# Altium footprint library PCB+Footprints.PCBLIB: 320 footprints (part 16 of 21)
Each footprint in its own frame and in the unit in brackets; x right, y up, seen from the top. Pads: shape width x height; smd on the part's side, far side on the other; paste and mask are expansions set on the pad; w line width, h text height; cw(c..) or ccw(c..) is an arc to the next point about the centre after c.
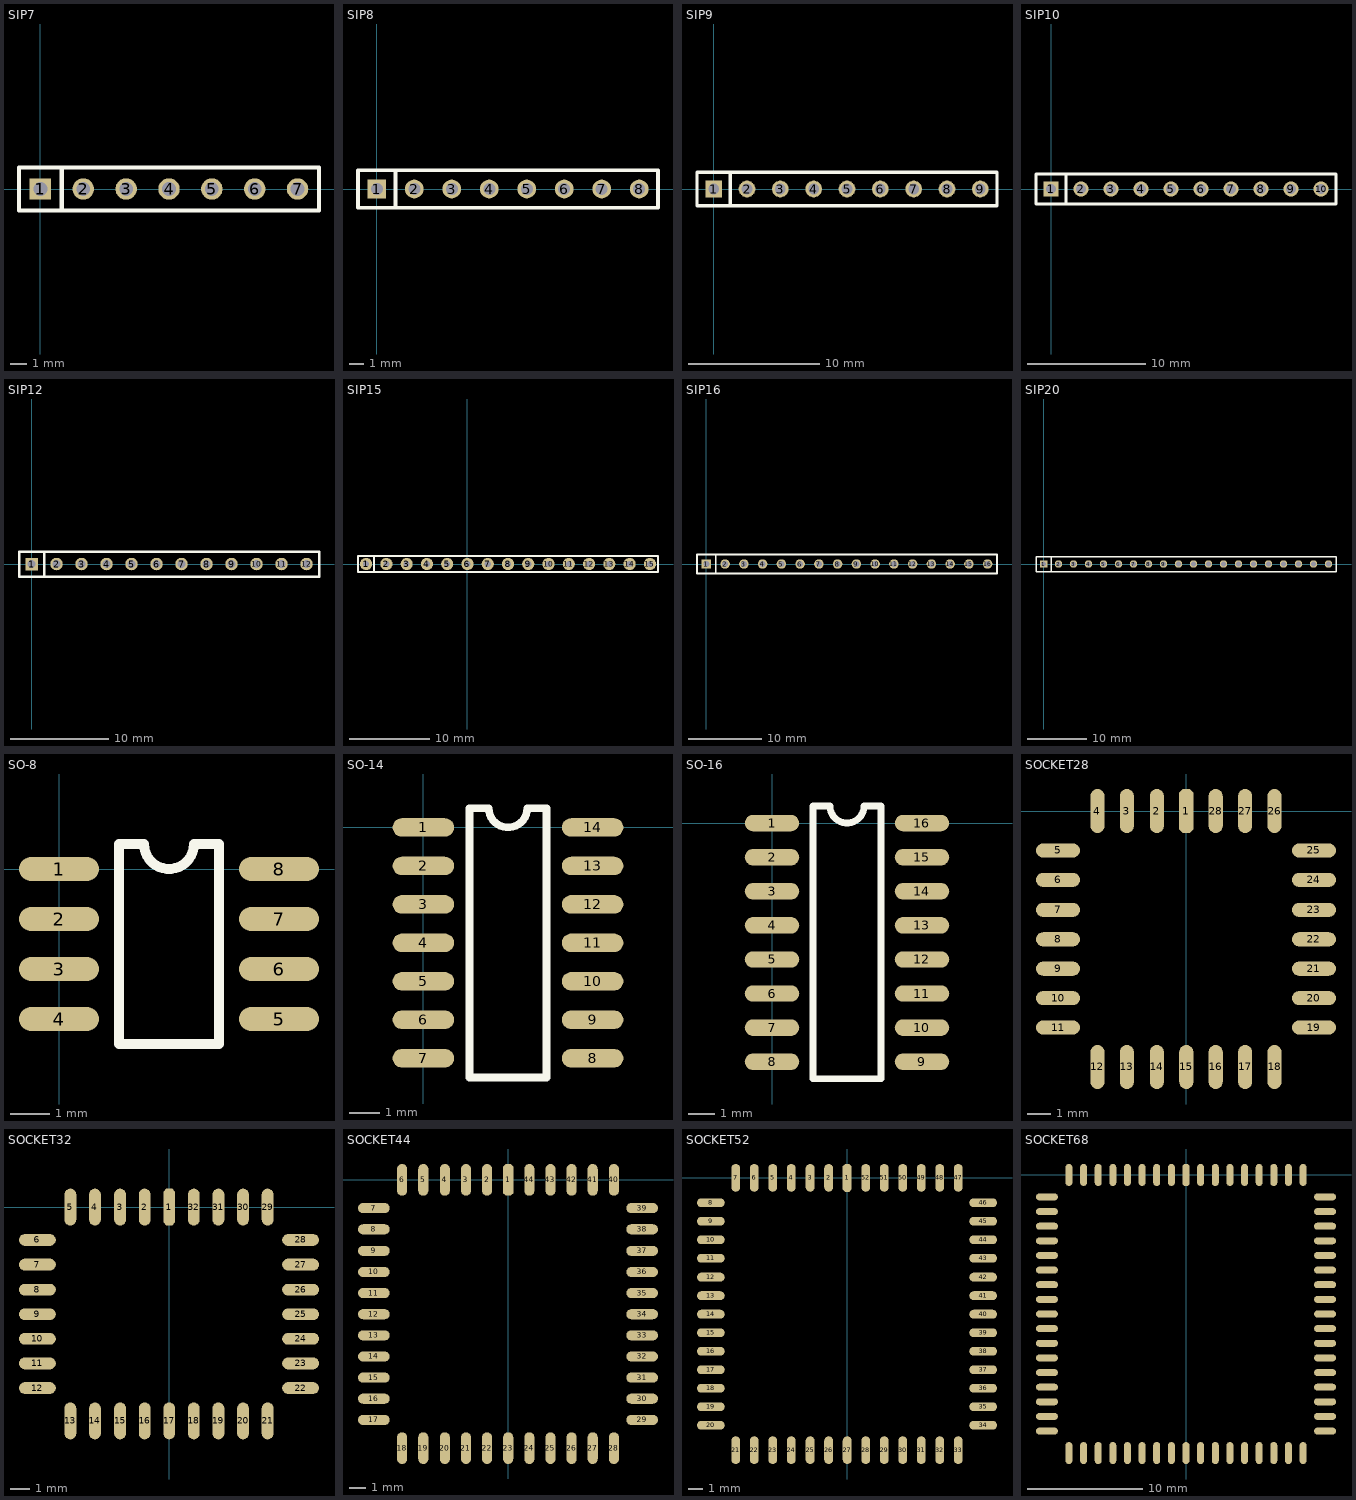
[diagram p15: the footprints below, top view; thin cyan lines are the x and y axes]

## SIP7 [mil]
pads (7):
  rect 50x50 hole 32: 1(0,0)
  round 50 hole 32: 2(100,0) 3(200,0) 4(300,0) 5(400,0) 6(500,0) 7(600,0)
TopOverlay:
  lines w10: 50,-50 50,50 ; -50,-50 650,-50 650,50 -50,50 -50,-50

## SIP8 [mil]
pads (8):
  rect 50x50 hole 32: 1(0,0)
  round 50 hole 32: 2(100,0) 3(200,0) 4(300,0) 5(400,0) 6(500,0) 7(600,0) 8(700,0)
TopOverlay:
  lines w10: 50,-50 50,50 ; -50,-50 -50,50 750,50 750,-50 -50,-50

## SIP9 [mil]
pads (9):
  rect 50x50 hole 32: 1(0,0)
  round 50 hole 32: 2(100,0) 3(200,0) 4(300,0) 5(400,0) 6(500,0) 7(600,0) 8(700,0) 9(800,0)
TopOverlay:
  lines w10: 50,-50 50,50 ; -50,-50 -50,50 850,50 850,-50 -50,-50

## SIP10 [mil]
pads (10):
  rect 50x50 hole 32: 1(0,0)
  round 50 hole 32: 2(100,0) 3(200,0) 4(300,0) 5(400,0) 6(500,0) 7(600,0) 8(700,0) 9(800,0) 10(900,0)
TopOverlay:
  lines w10: 50,-50 50,50 ; -50,-50 -50,50 950,50 950,-50 -50,-50

## SIP12 [mil]
pads (12):
  rect 50x50 hole 32: 1(0,0)
  round 50 hole 32: 2(100,0) 3(200,0) 4(300,0) 5(400,0) 6(500,0) 7(600,0) 8(700,0) 9(800,0) 10(900,0) 11(1000,0) 12(1100,0)
TopOverlay:
  lines w10: 50,-50 50,50 ; -50,-50 -50,50 1150,50 1150,-50 -50,-50

## SIP15 [mil]
pads (15):
  round 60 hole 30: 1(-500,0) 2(-400,0) 3(-300,0) 4(-200,0) 5(-100,0) 6(0,0) 7(100,0) 8(200,0) 9(300,0) 10(400,0) 11(500,0) 12(600,0) 13(700,0) 14(800,0) 15(900,0)
TopOverlay:
  lines w10: -460,-40 940,-40 940,40 -460,40 ; -460,-40 -460,40 ; -460,-40 -540,-40 -540,40 -460,40

## SIP16 [mil]
pads (16):
  rect 50x50 hole 32: 1(0,0)
  round 50 hole 32: 2(100,0) 3(200,0) 4(300,0) 5(400,0) 6(500,0) 7(600,0) 8(700,0) 9(800,0) 10(900,0) 11(1000,0) 12(1100,0) 13(1200,0) 14(1300,0) 15(1400,0) 16(1500,0)
TopOverlay:
  lines w10: 50,-50 50,50 ; -50,-50 1550,-50 1550,50 -50,50 -50,-50

## SIP20 [mil]
pads (20):
  rect 50x50 hole 32: 1(0,0)
  round 50 hole 32: 2(100,0) 3(200,0) 4(300,0) 5(400,0) 6(500,0) 7(600,0) 8(700,0) 9(800,0) 10(900,0) 11(1000,0) 12(1100,0) 13(1200,0) 14(1300,0) 15(1400,0) 16(1500,0) 17(1600,0) 18(1700,0) 19(1800,0) 20(1900,0)
TopOverlay:
  lines w10: 50,-50 50,50 ; -50,-50 -50,50 1950,50 1950,-50 -50,-50

## SO-8 [mil]
pads (8):
  oval 80x24 smd: 1(0,0) 2(0,-50) 3(0,-100) 4(0,-150) 5(220,-150) 6(220,-100) 7(220,-50) 8(220,0)
TopOverlay:
  lines w10: 60,-175 160,-175 160,25 135,25 cw(c110,25) 85,25 60,25 60,-175

## SO-14 [mil]
pads (14):
  oval 80x24 smd: 1(0,0) 2(0,-50) 3(0,-100) 4(0,-150) 5(0,-200) 6(0,-250) 7(0,-300) 8(220,-300) 9(220,-250) 10(220,-200) 11(220,-150) 12(220,-100) 13(220,-50) 14(220,0)
TopOverlay:
  lines w10: 60,25 60,25 ; 60,25 60,-325 160,-325 160,25 135,25 cw(c110,25) 85,25 60,25

## SO-16 [mil]
pads (16):
  oval 80x24 smd: 1(0,0) 2(0,-50) 3(0,-100) 4(0,-150) 5(0,-200) 6(0,-250) 7(0,-300) 8(0,-350) 9(220,-350) 10(220,-300) 11(220,-250) 12(220,-200) 13(220,-150) 14(220,-100) 15(220,-50) 16(220,0)
TopOverlay:
  lines w10: 60,25 60,25 ; 60,25 60,-375 160,-375 160,25 135,25 cw(c110,25) 85,25 60,25

## SOCKET28 [mil]
pads (28):
  oct 24x75 smd: 1(0,0)
  oval 24x75 smd: 2(-50,0) 3(-101,0) 4(-151,0) 12(-151,-435) 13(-101,-435) 14(-50,-435) 15(0,-435) 16(50,-435) 17(100,-435) 18(150,-435) 26(150,0) 27(100,0) 28(50,0)
  oval 75x24 smd: 5(-218,-67) 6(-218,-117) 7(-218,-168) 8(-218,-218) 9(-218,-268) 10(-218,-318) 11(-218,-368) 19(217,-368) 20(217,-318) 21(217,-268) 22(217,-218) 23(217,-168) 24(217,-117) 25(217,-67)

## SOCKET32 [mil]
pads (32):
  oct 24x75 smd: 1(0,0)
  oval 24x75 smd: 2(-50,0) 3(-100,0) 4(-151,0) 5(-201,0) 13(-201,-435) 14(-151,-435) 15(-100,-435) 16(-50,-435) 17(0,-435) 18(50,-435) 19(100,-435) 20(150,-435) 21(200,-435) 29(200,0) 30(150,0) 31(100,0) 32(50,0)
  oval 75x24 smd: 6(-268,-67) 7(-268,-117) 8(-268,-168) 9(-268,-218) 10(-268,-268) 11(-268,-318) 12(-268,-368) 22(267,-368) 23(267,-318) 24(267,-268) 25(267,-218) 26(267,-168) 27(267,-117) 28(267,-67)

## SOCKET44 [mil]
pads (44):
  oct 24x75 smd: 1(0,0)
  oval 24x75 smd: 2(-50,0) 3(-100,0) 4(-150,0) 5(-201,0) 6(-251,0) 18(-251,-635) 19(-201,-635) 20(-150,-635) 21(-100,-635) 22(-50,-635) 23(0,-635) 24(50,-635) 25(100,-635) 26(150,-635) 27(200,-635) 28(250,-635) 40(250,0) 41(200,0) 42(150,0) 43(100,0) 44(50,0)
  oval 75x24 smd: 7(-318,-67) 8(-318,-117) 9(-318,-168) 10(-318,-218) 11(-318,-268) 12(-318,-318) 13(-318,-368) 14(-318,-418) 15(-318,-468) 16(-318,-518) 17(-318,-568) 29(317,-568) 30(317,-518) 31(317,-468) 32(317,-418) 33(317,-368) 34(317,-318) 35(317,-268) 36(317,-218) 37(317,-168) 38(317,-117) 39(317,-67)

## SOCKET52 [mil]
pads (52):
  oct 24x75 smd: 1(0,0)
  oval 24x75 smd: 2(-50,0) 3(-100,0) 4(-151,0) 5(-201,0) 6(-251,0) 7(-301,0) 21(-301,-735) 22(-251,-735) 23(-201,-735) 24(-151,-735) 25(-100,-735) 26(-50,-735) 27(0,-735) 28(50,-735) 29(100,-735) 30(150,-735) 31(200,-735) 32(250,-735) 33(300,-735) 47(300,0) 48(250,0) 49(200,0) 50(150,0) 51(100,0) 52(50,0)
  oval 75x24 smd: 8(-368,-67) 9(-368,-117) 10(-368,-167) 11(-368,-217) 12(-368,-268) 13(-368,-318) 14(-368,-368) 15(-368,-418) 16(-368,-468) 17(-368,-518) 18(-368,-568) 19(-368,-618) 20(-368,-668) 34(367,-668) 35(367,-618) 36(367,-568) 37(367,-518) 38(367,-468) 39(367,-418) 40(367,-368) 41(367,-318) 42(367,-268) 43(367,-217) 44(367,-167) 45(367,-117) 46(367,-67)

## SOCKET68 [mil]
pads (68):
  oct 24x75 smd: 1(0,0)
  oval 24x75 smd: 2(-50,0) 3(-100,0) 4(-150,0) 5(-200,0) 6(-250,0) 7(-300,0) 8(-350,0) 9(-400,0) 27(-400,-950) 28(-350,-950) 29(-300,-950) 30(-250,-950) 31(-200,-950) 32(-150,-950) 33(-100,-950) 34(-50,-950) 35(0,-950) 36(50,-950) 37(100,-950) 38(150,-950) 39(200,-950) 40(250,-950) 41(300,-950) 42(350,-950) 43(400,-950) 61(400,0) 62(350,0) 63(300,0) 64(250,0) 65(200,0) 66(150,0) 67(100,0) 68(50,0)
  oval 75x24 smd: 10(-475,-75) 11(-475,-125) 12(-475,-175) 13(-475,-225) 14(-475,-275) 15(-475,-325) 16(-475,-375) 17(-475,-425) 18(-475,-475) 19(-475,-525) 20(-475,-575) 21(-475,-625) 22(-475,-675) 23(-475,-725) 24(-475,-775) 25(-475,-825) 26(-475,-875) 44(475,-875) 45(475,-825) 46(475,-775) 47(475,-725) 48(475,-675) 49(475,-625) 50(475,-575) 51(475,-525) 52(475,-475) 53(475,-425) 54(475,-375) 55(475,-325) 56(475,-275) 57(475,-225) 58(475,-175) 59(475,-125) 60(475,-75)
